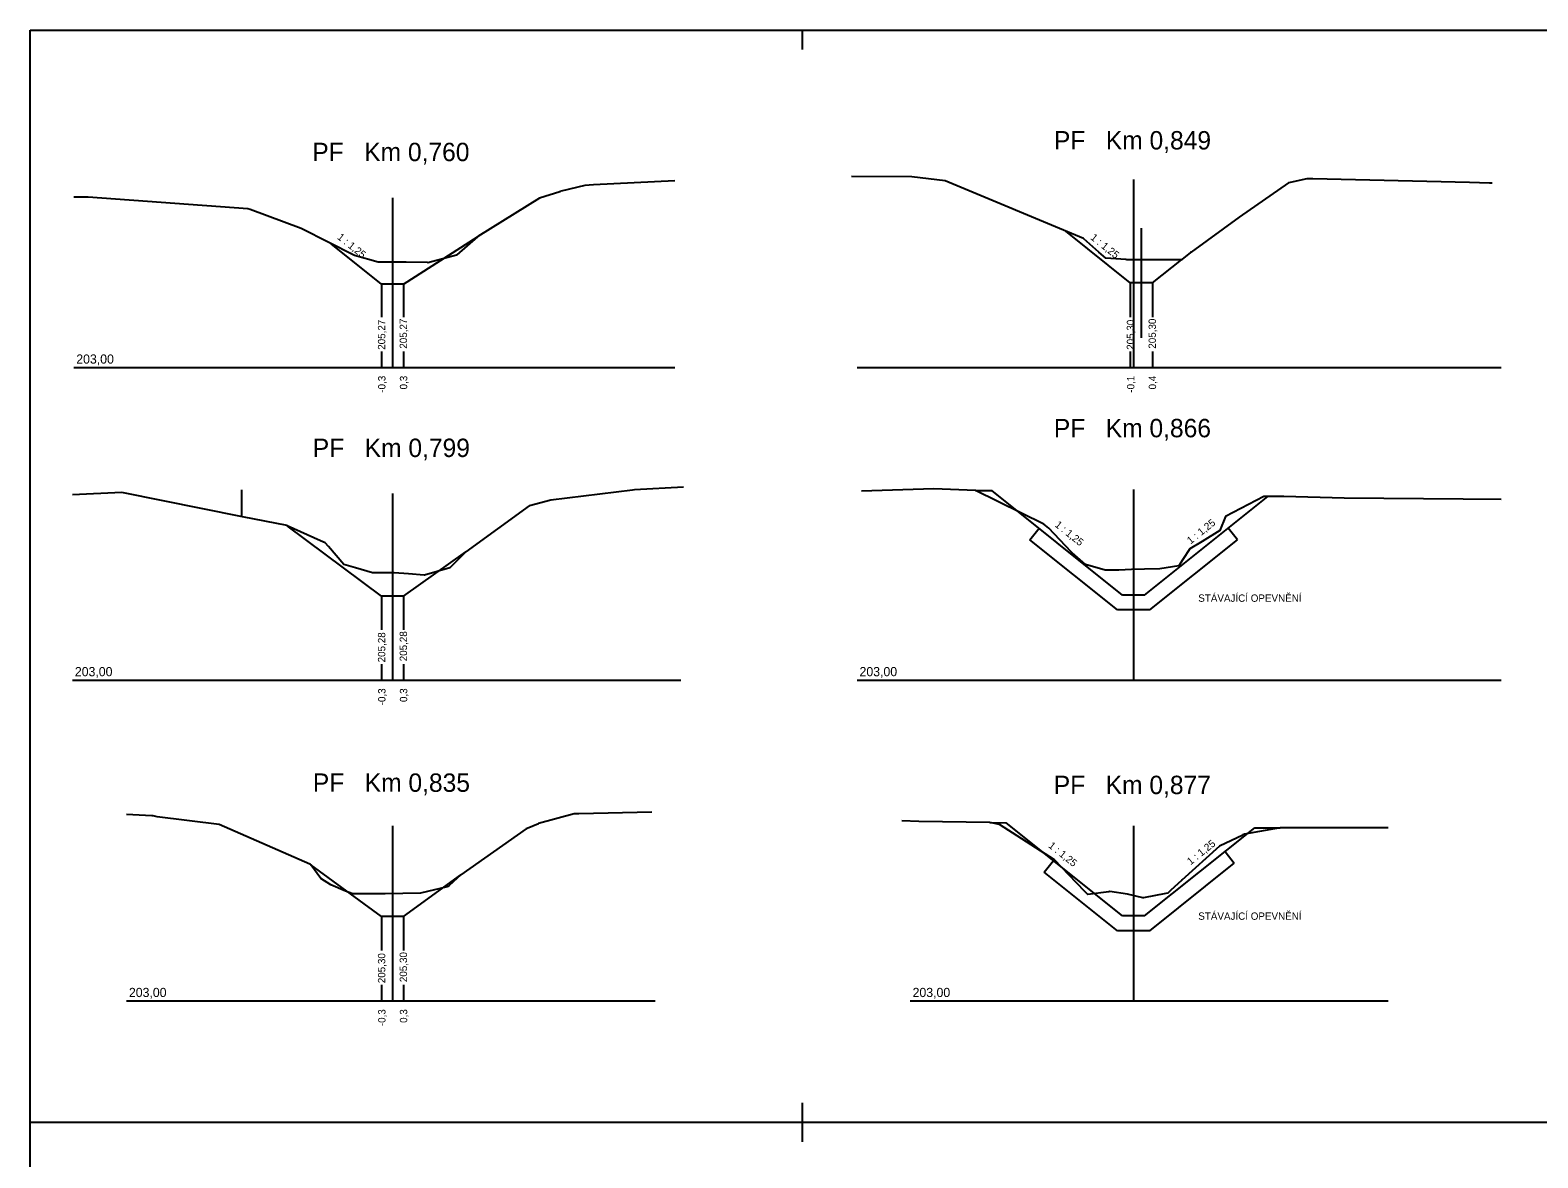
# Model space of a CAD drawing. Extents: x -547174 to -543113, y -1125006 to -1123643.
# Drawn here: x -547152.27 to -547111.27, y -1123741.01 to -1123710.35 of the extents above; entities that cross this region are included whole.
import ezdxf

# ---------------------------------------------------------------- set-up
doc = ezdxf.new("R2010")
doc.units = 0
for name, color, linetype in [('Default', 7, 'Continuous'), ('Profile', 7, 'Continuous'), ('PROFILY NÁVRH', 7, 'Continuous'), ('Section', 7, 'Continuous')]:
    doc.layers.add(name, color=color, linetype=linetype)

msp = doc.modelspace()

# ---------------------------------------------------------------- linework, layer by layer
at = {"layer": 'Default'}
for points in [[(-547134.742, -1123714.442), (-547136.947, -1123714.557), (-547137.189, -1123714.567), (-547137.826, -1123714.727), (-547137.836, -1123714.73), (-547137.85, -1123714.733), (-547137.853, -1123714.734), (-547137.863, -1123714.738), (-547137.864, -1123714.739), (-547137.868, -1123714.74), (-547138.423, -1123714.919), (-547140.097, -1123715.962), (-547140.109, -1123715.971), (-547140.67, -1123716.458), (-547140.672, -1123716.46), (-547140.676, -1123716.461), (-547141.457, -1123716.67), (-547141.467, -1123716.669), (-547142.048, -1123716.66), (-547142.782, -1123716.659), (-547142.79, -1123716.659), (-547142.81, -1123716.654), (-547143.454, -1123716.479), (-547144.881, -1123715.751), (-547144.896, -1123715.741), (-547144.904, -1123715.737), (-547146.288, -1123715.222), (-547146.354, -1123715.208), (-547150.691, -1123714.885), (-547151.082, -1123714.886)], [(-547112.508, -1123714.509), (-547112.583, -1123714.507), (-547113.122, -1123714.487), (-547117.39, -1123714.389), (-547117.548, -1123714.392), (-547118.005, -1123714.488), (-547118.04, -1123714.497), (-547118.051, -1123714.502), (-547119.392, -1123715.43), (-547120.693, -1123716.38), (-547120.716, -1123716.396), (-547120.945, -1123716.583), (-547120.95, -1123716.588), (-547121.565, -1123716.588), (-547121.575, -1123716.59), (-547121.588, -1123716.591), (-547122.08, -1123716.591), (-547122.435, -1123716.591), (-547122.449, -1123716.591), (-547122.475, -1123716.583), (-547123.015, -1123716.548), (-547123.016, -1123716.547), (-547123.206, -1123716.388), (-547123.615, -1123716.02), (-547123.623, -1123716.016), (-547127.39, -1123714.448), (-547128.296, -1123714.333), (-547129.938, -1123714.323)], [(-547134.499, -1123722.778), (-547135.833, -1123722.85), (-547135.891, -1123722.854), (-547138.108, -1123723.129), (-547138.109, -1123723.131), (-547138.694, -1123723.281), (-547138.695, -1123723.281), (-547138.696, -1123723.282), (-547140.421, -1123724.531), (-547140.421, -1123724.531), (-547140.855, -1123724.971), (-547141.548, -1123725.169), (-547141.555, -1123725.171), (-547141.986, -1123725.134), (-547142.37, -1123725.101), (-547142.954, -1123725.101), (-547142.957, -1123725.101), (-547143.427, -1123724.97), (-547143.744, -1123724.881), (-547144.159, -1123724.392), (-547144.245, -1123724.291), (-547144.375, -1123724.232), (-547145.278, -1123723.822), (-547145.282, -1123723.821), (-547146.501, -1123723.577), (-547149.78, -1123722.922), (-547151.118, -1123722.987), (-547151.12, -1123722.987)], [(-547112.261, -1123723.112), (-547113.302, -1123723.102), (-547116.537, -1123723.076), (-547118.172, -1123723.032), (-547118.627, -1123723.027), (-547118.721, -1123723.032), (-547119.76, -1123723.569), (-547119.919, -1123723.951), (-547120.392, -1123724.25), (-547120.728, -1123724.451), (-547120.926, -1123724.744), (-547121.031, -1123724.917), (-547121.545, -1123725), (-547121.961, -1123725.001), (-547122.315, -1123725.014), (-547122.667, -1123725.028), (-547123.032, -1123725.03), (-547123.569, -1123724.874), (-547123.935, -1123724.556), (-547123.96, -1123724.531), (-547124.568, -1123723.892), (-547124.703, -1123723.782), (-547126.562, -1123722.869), (-547127.691, -1123722.821), (-547129.663, -1123722.884)], [(-547135.365, -1123731.615), (-547137.349, -1123731.658), (-547137.474, -1123731.661), (-547138.448, -1123731.925), (-547138.449, -1123731.926), (-547138.751, -1123732.054), (-547138.78, -1123732.066), (-547138.78, -1123732.066), (-547138.78, -1123732.066), (-547140.557, -1123733.318), (-547140.558, -1123733.319), (-547140.878, -1123733.608), (-547140.909, -1123733.636), (-547140.932, -1123733.642), (-547141.654, -1123733.816), (-547142.618, -1123733.836), (-547142.628, -1123733.836), (-547142.636, -1123733.836), (-547143.493, -1123733.836), (-547143.52, -1123733.827), (-547143.694, -1123733.759), (-547144.097, -1123733.586), (-547144.369, -1123733.42), (-547144.638, -1123733.046), (-547144.646, -1123733.036), (-547144.664, -1123733.028), (-547147.13, -1123731.952), (-547148.821, -1123731.736), (-547148.93, -1123731.714), (-547148.963, -1123731.716), (-547149.649, -1123731.674)], [(-547115.337, -1123732.041), (-547115.491, -1123732.041), (-547118.279, -1123732.04), (-547119.241, -1123732.213), (-547119.287, -1123732.233), (-547119.29, -1123732.234), (-547119.925, -1123732.537), (-547120.952, -1123733.461), (-547120.957, -1123733.464), (-547120.962, -1123733.468), (-547121.249, -1123733.736), (-547121.333, -1123733.814), (-547121.381, -1123733.824), (-547121.991, -1123733.943), (-547121.992, -1123733.943), (-547122.004, -1123733.945), (-547122.01, -1123733.945), (-547122.428, -1123733.84), (-547122.907, -1123733.775), (-547122.937, -1123733.776), (-547123.507, -1123733.848), (-547123.575, -1123733.78), (-547123.813, -1123733.538), (-547124.41, -1123732.907), (-547125.3, -1123732.337), (-547125.904, -1123731.95), (-547126.174, -1123731.896), (-547128.104, -1123731.869), (-547128.567, -1123731.853)]]:
    msp.add_lwpolyline(points, dxfattribs=at)
at = {"layer": 'Profile'}
for p, q in [((-547152.272, -1123710.346), (-547131.272, -1123710.346)), ((-547152.272, -1123740.046), (-547152.272, -1123710.346)), ((-547131.272, -1123710.346), (-547110.272, -1123710.346)), ((-547131.272, -1123710.346), (-547131.272, -1123710.874)), ((-547131.272, -1123739.518), (-547131.272, -1123740.046)), ((-547152.272, -1123740.046), (-547138.818, -1123740.046)), ((-547152.272, -1123740.046), (-547131.272, -1123740.046)), ((-547152.272, -1123769.746), (-547152.272, -1123740.046)), ((-547131.272, -1123740.046), (-547115.303, -1123740.046)), ((-547131.272, -1123740.046), (-547110.272, -1123740.046)), ((-547131.272, -1123740.046), (-547131.272, -1123740.574))]:
    msp.add_line(p, q, dxfattribs=at)
at = {"layer": 'PROFILY NÁVRH'}
for p, q in [((-547122.35, -1123717.22), (-547124.106, -1123715.815)), ((-547122.05, -1123718.711), (-547122.05, -1123715.73)), ((-547142.718, -1123717.25), (-547144.081, -1123716.159)), ((-547142.118, -1123717.25), (-547140.109, -1123715.971)), ((-547121.75, -1123717.22), (-547120.959, -1123716.588)), ((-547142.118, -1123717.25), (-547142.718, -1123717.25)), ((-547142.718, -1123717.25), (-547142.718, -1123718.152)), ((-547142.118, -1123717.25), (-547142.118, -1123718.152)), ((-547121.75, -1123717.22), (-547122.35, -1123717.22)), ((-547122.35, -1123717.22), (-547122.35, -1123718.152)), ((-547121.75, -1123717.22), (-547121.75, -1123718.152)), ((-547142.718, -1123719.087), (-547142.718, -1123719.52)), ((-547142.118, -1123719.087), (-547142.118, -1123719.52)), ((-547122.35, -1123719.087), (-547122.35, -1123719.52)), ((-547121.75, -1123719.087), (-547121.75, -1123719.52)), ((-547146.518, -1123723.574), (-547146.518, -1123722.849)), ((-547126.562, -1123722.869), (-547126.113, -1123722.869)), ((-547122.561, -1123725.711), (-547126.113, -1123722.869)), ((-547121.961, -1123725.711), (-547118.606, -1123723.027)), ((-547142.718, -1123725.741), (-547145.278, -1123723.822)), ((-547125.082, -1123724.206), (-547124.832, -1123723.894)), ((-547119.439, -1123724.206), (-547119.689, -1123723.894)), ((-547142.118, -1123725.741), (-547140.421, -1123724.531)), ((-547122.701, -1123726.111), (-547125.082, -1123724.206)), ((-547121.82, -1123726.111), (-547119.439, -1123724.206)), ((-547142.118, -1123725.741), (-547142.718, -1123725.741)), ((-547142.718, -1123725.741), (-547142.718, -1123726.652)), ((-547142.118, -1123725.741), (-547142.118, -1123726.652)), ((-547121.961, -1123725.711), (-547122.561, -1123725.711)), ((-547121.82, -1123726.111), (-547122.701, -1123726.111)), ((-547142.718, -1123727.587), (-547142.718, -1123728.021)), ((-547142.118, -1123727.587), (-547142.118, -1123728.021)), ((-547126.174, -1123731.896), (-547125.728, -1123731.902)), ((-547122.561, -1123734.436), (-547125.728, -1123731.902)), ((-547121.961, -1123734.436), (-547118.966, -1123732.04)), ((-547118.966, -1123732.04), (-547118.279, -1123732.04)), ((-547119.774, -1123732.687), (-547119.524, -1123732.999)), ((-547142.718, -1123734.446), (-547144.638, -1123733.046)), ((-547124.692, -1123733.243), (-547124.442, -1123732.931)), ((-547121.82, -1123734.836), (-547119.524, -1123732.999)), ((-547142.118, -1123734.446), (-547140.558, -1123733.319)), ((-547122.701, -1123734.836), (-547124.692, -1123733.243)), ((-547142.118, -1123734.446), (-547142.718, -1123734.446)), ((-547142.718, -1123734.446), (-547142.718, -1123735.377)), ((-547142.118, -1123734.446), (-547142.118, -1123735.377)), ((-547121.961, -1123734.436), (-547122.561, -1123734.436)), ((-547121.82, -1123734.836), (-547122.701, -1123734.836)), ((-547142.718, -1123736.312), (-547142.718, -1123736.746)), ((-547142.118, -1123736.312), (-547142.118, -1123736.746))]:
    msp.add_line(p, q, dxfattribs=at)
at = {"layer": 'Section'}
for p, q in [((-547122.261, -1123714.412), (-547122.261, -1123719.52)), ((-547142.418, -1123714.903), (-547142.418, -1123719.52)), ((-547151.081, -1123719.52), (-547134.742, -1123719.52)), ((-547129.778, -1123719.52), (-547112.261, -1123719.52)), ((-547122.261, -1123722.835), (-547122.261, -1123728.021)), ((-547142.418, -1123722.948), (-547142.418, -1123728.021)), ((-547151.12, -1123728.021), (-547134.573, -1123728.021)), ((-547129.778, -1123728.021), (-547112.261, -1123728.021)), ((-547142.418, -1123731.985), (-547142.418, -1123736.746)), ((-547122.261, -1123731.989), (-547122.261, -1123736.746)), ((-547149.649, -1123736.746), (-547135.269, -1123736.746)), ((-547128.336, -1123736.746), (-547115.337, -1123736.746))]:
    msp.add_line(p, q, dxfattribs=at)

# ---------------------------------------------------------------- texts
at = {"layer": 'PROFILY NÁVRH'}
for s, rotation, p in [('1 : 1,25', 321.3402, (-547143.937, -1123716.007)), ('1 : 1,25', 321.3402, (-547123.45, -1123716.017)), ('205,27', 90, (-547142.614, -1123719.039)), ('205,27', 90, (-547142.022, -1123719.009)), ('205,30', 90, (-547122.246, -1123719.039)), ('205,30', 90, (-547121.654, -1123719.009)), ('-0,3', 90, (-547142.608, -1123720.206)), ('0,3', 90, (-547142.017, -1123720.117)), ('-0,1', 90, (-547122.24, -1123720.206)), ('0,4', 90, (-547121.649, -1123720.117)), ('1 : 1,25', 38.6598, (-547120.711, -1123724.335)), ('1 : 1,25', 321.3402, (-547124.419, -1123723.83)), ('205,28', 90, (-547142.614, -1123727.54)), ('205,28', 90, (-547142.022, -1123727.51)), ('-0,3', 90, (-547142.608, -1123728.707)), ('0,3', 90, (-547142.017, -1123728.618)), ('1 : 1,25', 321.3402, (-547124.594, -1123732.555)), ('1 : 1,25', 38.6598, (-547120.711, -1123733.06)), ('205,30', 90, (-547142.614, -1123736.265)), ('205,30', 90, (-547142.022, -1123736.235)), ('-0,3', 90, (-547142.608, -1123737.432)), ('0,3', 90, (-547142.017, -1123737.343))]:
    msp.add_text(s, height=0.2, rotation=rotation, dxfattribs=at).set_placement(p)
for p in [(-547120.502, -1123725.892), (-547120.502, -1123734.54)]:
    msp.add_text('STÁVAJÍCÍ OPEVNĚNÍ', height=0.2, dxfattribs=at).set_placement(p)
at = {"layer": 'Section'}
for s, height, p in [('PF   Km 0,760', 0.5, (-547144.598, -1123713.909)), ('PF   Km 0,849', 0.5, (-547124.428, -1123713.591)), ('203,00', 0.25, (-547151.018, -1123719.415)), ('PF   Km 0,866', 0.5, (-547124.43, -1123721.418)), ('PF   Km 0,799', 0.5, (-547144.585, -1123721.955)), ('203,00', 0.25, (-547151.056, -1123727.916)), ('203,00', 0.25, (-547129.715, -1123727.916)), ('PF   Km 0,835', 0.5, (-547144.584, -1123731.06)), ('PF   Km 0,877', 0.5, (-547124.432, -1123731.122)), ('203,00', 0.25, (-547149.586, -1123736.641)), ('203,00', 0.25, (-547128.272, -1123736.641))]:
    msp.add_text(s, height=height, dxfattribs=at).set_placement(p)

doc.saveas('drawing.dxf')
